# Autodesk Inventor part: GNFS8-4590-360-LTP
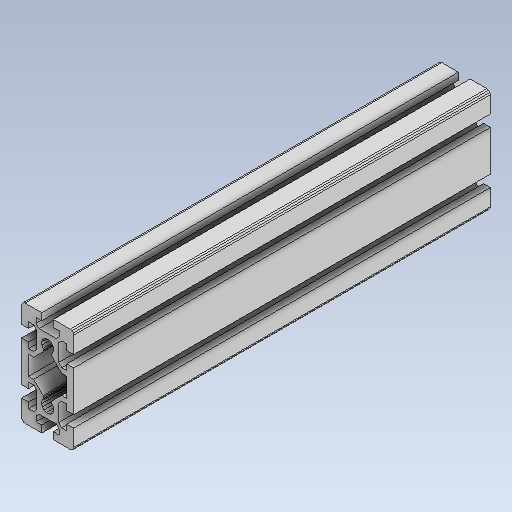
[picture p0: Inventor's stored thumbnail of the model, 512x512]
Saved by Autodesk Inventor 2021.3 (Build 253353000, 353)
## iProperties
Created: 2022-02
Part Number: GNFS8-4590-360-LTP
Material: 一般
Document SubType Name: Modeling
Designer: kengo
Density: 1 g/cm^3
Appearance: 既定
Author: kengo
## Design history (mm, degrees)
feature "GNFS8-4590-360-LTP"
node "ソリッド1"
